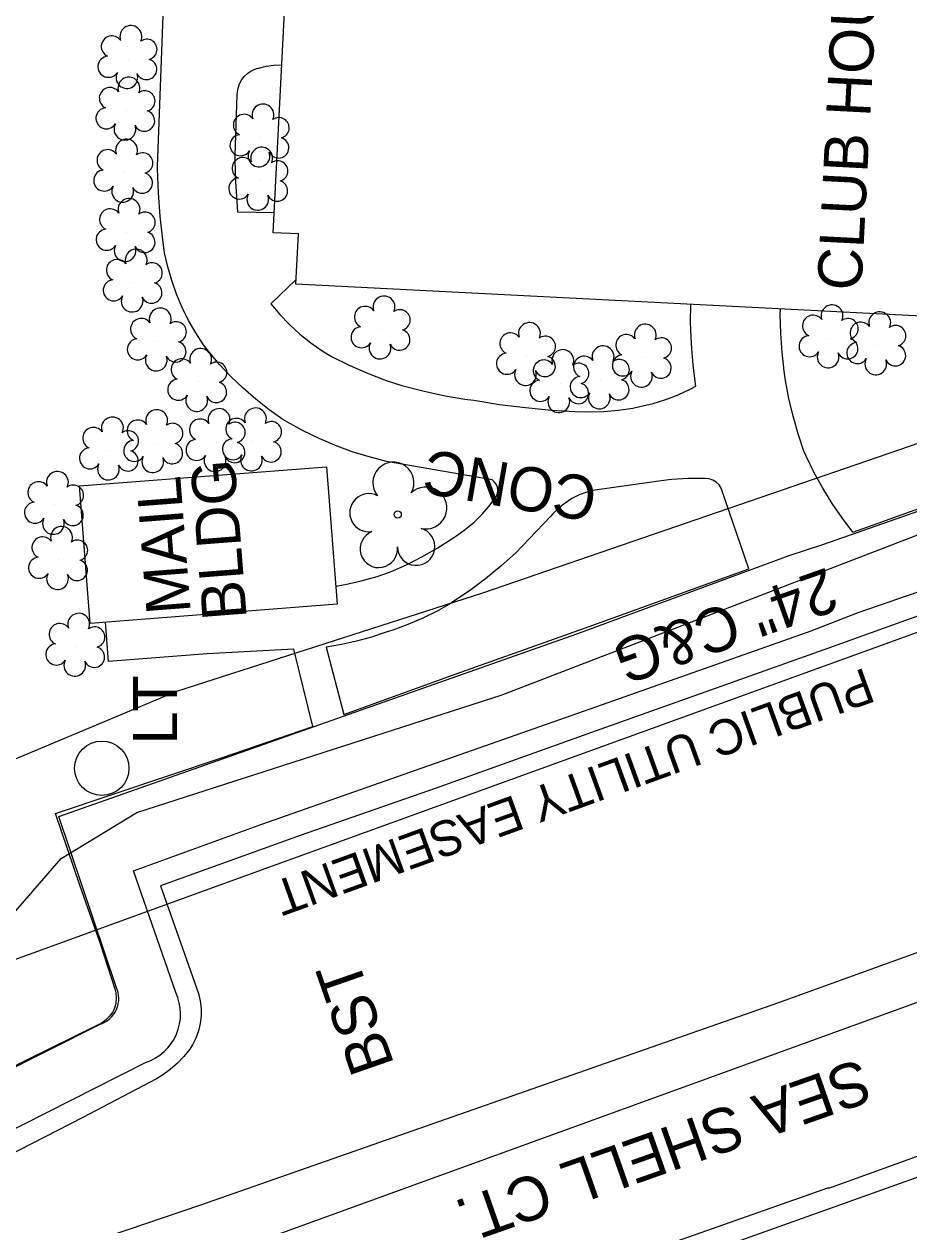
# Model space of a CAD drawing. Extents: x 1614611 to 1617571, y 898867 to 905462.
# Drawn here: x 1616410.3 to 1616490.5, y 903640.3 to 903749 of the extents above; entities that cross this region are included whole.
import ezdxf

# ---------------------------------------------------------------- set-up
doc = ezdxf.new("R2010")
doc.units = 0
for name, color, linetype in [('Exist Boundary Watershed Residential C 05', 7, 'Continuous'), ('Exist Building', 7, 'Continuous'), ('Exist Building Text', 7, 'Continuous'), ('Exist Other Culture Area Outline', 7, 'Continuous'), ('Exist Right of Way Easement Line Text', 7, 'Continuous'), ('Exist Roads EOP Text', 7, 'Continuous'), ('Exist Utilities Other Pole CELL', 7, 'Continuous'), ('Exist Utilities Other Pole Text', 7, 'Continuous'), ('Exist Utilities Telephone UG FO SUE LOS B', 7, 'Continuous'), ('Exist Utilities TV UG FO Cable SUE LOS B', 7, 'Continuous'), ('Exist Utilities Water UG Line SUE LOS B', 7, 'Continuous'), ('Exist Vegetation Shrub CELL', 7, 'Continuous'), ('Exist Vegetation Tree CELL', 7, 'Continuous'), ('Prop Earthen Structure Cut Ditch Special Back of Curb Detail CELL', 7, 'Continuous'), ('Raster_Level_2', 7, 'Continuous'), ('Scratch_Level_1', 7, 'Continuous'), ('Scratch_Level_9', 7, 'Continuous')]:
    doc.layers.add(name, color=color, linetype=linetype)

msp = doc.modelspace()

# ---------------------------------------------------------------- linework, layer by layer
at = {"layer": 'Exist Boundary Watershed Residential C 05'}
msp.add_line((1616404.41, 903646.41), (1616421.34, 903654.97), dxfattribs=at)
for points in [[(1616424.06, 903661.29), (1616420.25, 903672.32), (1616431.85, 903676.54), (1616462.71, 903687.37), (1616481.6, 903694.05), (1616485.86, 903695.71), (1616492.24, 903697.91), (1616511.21, 903704.68), (1616512.84, 903699.7), (1616514.71, 903694.52), (1616516.59, 903689.23)], [(1616522.28, 903655.67), (1616483.74, 903641.89), (1616444.61, 903627.92), (1616416.59, 903617.9)]]:
    msp.add_lwpolyline(points, dxfattribs=at)
msp.add_ellipse((1616419.91, 903659.33), major_axis=(4.56, 0.52), ratio=0.998402, start_param=4.915467, end_param=6.611675, dxfattribs=at)
at = {"layer": 'Exist Building'}
msp.add_lwpolyline([(1616497.51, 903722.23), (1616434.95, 903725.43), (1616435.18, 903729.98), (1616432.89, 903730.1), (1616434.76, 903766.57), (1616520.96, 903762.15), (1616519.1, 903725.79), (1616514.81, 903726.01), (1616514.57, 903721.36), (1616508.97, 903721.64)], dxfattribs=at)
msp.add_lwpolyline([(1616415.35, 903707.17), (1616437.72, 903708.9), (1616438.69, 903696.45), (1616416.31, 903694.72)], close=True, dxfattribs=at)
at = {"layer": 'Exist Other Culture Area Outline'}
for points in [[(1616438.56, 903698.09), (1616439.4, 903698.24), (1616440.86, 903698.58), (1616442.29, 903698.98), (1616443.52, 903699.4), (1616444.96, 903700.04), (1616446.36, 903700.75), (1616447.73, 903701.53), (1616449.06, 903702.37), (1616449.51, 903702.68), (1616450.31, 903703.25), (1616451.07, 903703.89), (1616451.78, 903704.58), (1616452.43, 903705.33), (1616453.02, 903706.12), (1616453.07, 903706.2), (1616453.19, 903706.47), (1616453.24, 903706.76), (1616453.2, 903707.05), (1616453.09, 903707.32), (1616452.91, 903707.55), (1616452.72, 903707.71), (1616450.62, 903708.09), (1616443.14, 903709.39), (1616441.58, 903709.79), (1616440.04, 903710.27), (1616438.53, 903710.83), (1616437.04, 903711.46), (1616435.6, 903712.16), (1616434.18, 903712.94), (1616433.77, 903713.18), (1616432.51, 903714.06), (1616431.31, 903715.01), (1616430.16, 903716.02), (1616429.05, 903717.08), (1616428.01, 903718.2), (1616427.03, 903719.38), (1616426.59, 903719.94), (1616425.87, 903721.03), (1616425.22, 903722.16), (1616424.64, 903723.32), (1616424.13, 903724.53), (1616423.7, 903725.76), (1616423.34, 903727.01), (1616423.06, 903728.28), (1616422.88, 903729.44), (1616422.65, 903731.58), (1616422.5, 903733.72), (1616422.42, 903735.87), (1616422.42, 903736.1), (1616423.02, 903752.18)], [(1616432.98, 903731.89), (1616429.69, 903731.97), (1616429.46, 903735.23), (1616429.43, 903737.12), (1616429.64, 903742.62), (1616429.68, 903743.06), (1616429.8, 903743.48), (1616430, 903743.88), (1616430.26, 903744.24), (1616430.59, 903744.54), (1616430.96, 903744.78), (1616431.37, 903744.95), (1616431.55, 903745), (1616432.25, 903745.18), (1616432.96, 903745.28), (1616433.67, 903745.3)], [(1616434.97, 903725.86), (1616432.66, 903723.65), (1616433.48, 903722.69), (1616434.36, 903721.78), (1616435.3, 903720.92), (1616436.29, 903720.13), (1616437.32, 903719.4), (1616438.16, 903718.88), (1616439.78, 903718.09), (1616441.43, 903717.37), (1616443.12, 903716.73), (1616444.55, 903716.25), (1616446.43, 903715.77), (1616448.32, 903715.37), (1616450.23, 903715.04), (1616451.05, 903714.92), (1616453.39, 903714.55), (1616455.74, 903714.26), (1616458.1, 903714.04), (1616460.19, 903713.91), (1616461.51, 903713.87), (1616462.83, 903713.91), (1616464.15, 903714.03), (1616465.46, 903714.22), (1616466.1, 903714.35), (1616467.28, 903714.63), (1616468.43, 903714.99), (1616469.55, 903715.42), (1616470.64, 903715.93), (1616471.15, 903716.19), (1616470.92, 903718.11), (1616470.76, 903720.04), (1616470.68, 903721.98), (1616470.69, 903723.6)], [(1616485.37, 903702.99), (1616484.4, 903704.27), (1616483.49, 903705.59), (1616482.65, 903706.96), (1616481.88, 903708.36), (1616481.18, 903709.8), (1616480.95, 903710.33), (1616480.42, 903711.9), (1616479.96, 903713.48), (1616479.58, 903715.09), (1616479.28, 903716.71), (1616479.15, 903717.57), (1616478.96, 903719.27), (1616478.84, 903720.98), (1616478.8, 903722.69), (1616478.81, 903723.19)], [(1616485.37, 903702.99), (1616487.68, 903703.79), (1616500.78, 903708.55), (1616508.93, 903711.47), (1616508.22, 903715.83), (1616507.68, 903719.46), (1616507.29, 903721.73)], [(1616402.13, 903650.99), (1616410.64, 903655.24), (1616416.83, 903658.28), (1616417.32, 903658.54), (1616417.76, 903658.87), (1616418.17, 903659.25), (1616418.36, 903659.48), (1616418.55, 903659.9), (1616418.67, 903660.34), (1616418.7, 903660.8), (1616418.66, 903661.26), (1616418.61, 903661.5), (1616417.24, 903665.71), (1616415.38, 903671.03), (1616413.19, 903677.5), (1616428.29, 903682.59), (1616436.48, 903685.38), (1616434.76, 903692.39), (1616426.9, 903691.97), (1616417.97, 903691.26), (1616417.71, 903694.83)]]:
    msp.add_lwpolyline(points, dxfattribs=at)
msp.add_lwpolyline([(1616439.28, 903686.47), (1616449.47, 903690.17), (1616461.51, 903694.43), (1616475.96, 903699.65), (1616473.45, 903706.97), (1616473.26, 903707.27), (1616473, 903707.52), (1616472.7, 903707.7), (1616472.36, 903707.82), (1616472, 903707.85), (1616471.94, 903707.85), (1616470.46, 903707.84), (1616468.99, 903707.75), (1616468.67, 903707.72), (1616462.02, 903706.79), (1616461.3, 903706.61), (1616460.6, 903706.35), (1616459.94, 903706.02), (1616459.31, 903705.62), (1616458.73, 903705.15), (1616458.2, 903704.63), (1616458.01, 903704.41), (1616454.84, 903701.09), (1616453.49, 903699.89), (1616452.1, 903698.75), (1616450.65, 903697.68), (1616449.16, 903696.67), (1616448.99, 903696.56), (1616447.72, 903695.84), (1616446.43, 903695.19), (1616445.09, 903694.62), (1616443.73, 903694.12), (1616443.13, 903693.93), (1616441.79, 903693.48), (1616440.44, 903693.1), (1616439.06, 903692.8), (1616437.68, 903692.58)], close=True, dxfattribs=at)
at = {"layer": 'Exist Utilities Other Pole CELL'}
msp.add_circle((1616417.37, 903681.61), 2.46, dxfattribs=at)
at = {"layer": 'Exist Utilities Telephone UG FO SUE LOS B'}
msp.add_lwpolyline([(1616368.82, 903664.38), (1616374.13, 903666.7), (1616400.24, 903678.58), (1616424.15, 903688.58), (1616451.87, 903697.49), (1616492.43, 903711.43), (1616524.09, 903720.83), (1616535.63, 903725.41), (1616539.88, 903728.72), (1616540.44, 903740.67), (1616541.79, 903762.56), (1616543.01, 903774.12), (1616544.39, 903782.9), (1616550.25, 903790.71), (1616577.87, 903805.8), (1616588.44, 903809.04)], dxfattribs=at)
at = {"layer": 'Exist Utilities TV UG FO Cable SUE LOS B'}
msp.add_lwpolyline([(1616409.28, 903583.28), (1616401.83, 903602.06), (1616396.84, 903616.07), (1616392.29, 903636.86), (1616392.86, 903647.11), (1616394.48, 903651.32), (1616413.7, 903673.44), (1616420.55, 903677.59), (1616453.53, 903688.22), (1616514.87, 903711.84), (1616526.07, 903715.66), (1616536.86, 903720.55), (1616545.52, 903724.83), (1616549.16, 903728.55), (1616549.91, 903729.9), (1616554.28, 903748.73), (1616554.29, 903750.67), (1616552.37, 903762.47), (1616557.09, 903779.98), (1616577.36, 903795.05), (1616590.41, 903803.23)], dxfattribs=at)
at = {"layer": 'Exist Utilities Water UG Line SUE LOS B'}
msp.add_lwpolyline([(1616350.21, 903616.94), (1616374.62, 903624.54), (1616426.35, 903642.07), (1616478.57, 903660.36), (1616520.74, 903675.61), (1616534.8, 903680.84), (1616536.9, 903682.38), (1616549.12, 903691.48), (1616560.45, 903718.95), (1616573.2, 903736.65), (1616589.15, 903758.02), (1616604.81, 903760.79)], dxfattribs=at)
at = {"layer": 'Exist Vegetation Shrub CELL'}
for p, q in [((1616419.77, 903745.82), (1616419.77, 903745.82)), ((1616419.59, 903741.15), (1616419.59, 903741.15)), ((1616431.73, 903738.72), (1616431.73, 903738.72)), ((1616419.39, 903735.53), (1616419.39, 903735.53)), ((1616431.62, 903734.81), (1616431.62, 903734.81)), ((1616419.61, 903730.16), (1616419.61, 903730.16)), ((1616420.25, 903725.58), (1616420.25, 903725.58)), ((1616442.69, 903721.33), (1616442.69, 903721.33)), ((1616483.26, 903720.53), (1616483.26, 903720.53)), ((1616422.43, 903720.24), (1616422.43, 903720.24)), ((1616487.58, 903719.9), (1616487.58, 903719.9)), ((1616455.86, 903718.93), (1616455.86, 903718.93)), ((1616466.35, 903718.78), (1616466.35, 903718.78)), ((1616426.09, 903716.58), (1616426.09, 903716.58)), ((1616458.88, 903716.48), (1616458.88, 903716.48)), ((1616462.53, 903716.82), (1616462.53, 903716.82)), ((1616422.11, 903711.04), (1616422.11, 903711.04)), ((1616427.75, 903711.14), (1616427.75, 903711.14)), ((1616431.05, 903711.2), (1616431.05, 903711.2)), ((1616418.1, 903710.38), (1616418.1, 903710.38)), ((1616413.12, 903705.45), (1616413.12, 903705.45)), ((1616413.49, 903700.47), (1616413.49, 903700.47)), ((1616415.05, 903692.61), (1616415.05, 903692.61))]:
    msp.add_line(p, q, dxfattribs=at)
for centre, radius, start, end in [((1616420, 903747.86), 0.99, 334.8391, 200.4717), ((1616418.29, 903746.95), 0.968, 35.8908, 245.4216), ((1616421.44, 903746.69), 0.929, 284.4567, 126.0861), ((1616417.97, 903745.12), 0.955, 95.1099, 327.9534), ((1616421.41, 903744.89), 0.937, 204.9913, 73.4601), ((1616419.64, 903744.14), 0.984, 151.2797, 21.387), ((1616419.82, 903743.19), 0.99, 334.8391, 200.4717), ((1616418.11, 903742.28), 0.968, 35.8908, 245.4216), ((1616421.26, 903742.02), 0.929, 284.4567, 126.0861), ((1616417.79, 903740.45), 0.955, 95.1099, 327.9534), ((1616421.22, 903740.22), 0.937, 204.9913, 73.4601), ((1616431.96, 903740.76), 0.99, 334.8391, 200.4717), ((1616419.46, 903739.47), 0.984, 151.2797, 21.387), ((1616430.25, 903739.85), 0.968, 35.8908, 245.4216), ((1616433.4, 903739.59), 0.929, 284.4567, 126.0861), ((1616429.93, 903738.02), 0.955, 95.1099, 327.9534), ((1616419.61, 903737.57), 0.99, 334.8391, 200.4717), ((1616431.85, 903736.85), 0.99, 334.8391, 200.4717), ((1616433.37, 903737.79), 0.937, 204.9913, 73.4601), ((1616417.9, 903736.65), 0.968, 35.8908, 245.4216), ((1616421.06, 903736.4), 0.929, 284.4567, 126.0861), ((1616430.14, 903735.93), 0.968, 35.8908, 245.4216), ((1616431.6, 903737.04), 0.984, 151.2797, 21.387), ((1616433.29, 903735.68), 0.929, 284.4567, 126.0861), ((1616417.59, 903734.82), 0.955, 95.1099, 327.9534), ((1616421.02, 903734.6), 0.937, 204.9913, 73.4601), ((1616429.82, 903734.1), 0.955, 95.1099, 327.9534), ((1616433.26, 903733.88), 0.937, 204.9913, 73.4601), ((1616419.26, 903733.84), 0.984, 151.2797, 21.387), ((1616431.49, 903733.12), 0.984, 151.2797, 21.387), ((1616418.13, 903731.29), 0.968, 35.8908, 245.4216), ((1616419.84, 903732.2), 0.99, 334.8391, 200.4717), ((1616421.28, 903731.03), 0.929, 284.4567, 126.0861), ((1616417.81, 903729.46), 0.955, 95.1099, 327.9534), ((1616421.25, 903729.23), 0.937, 204.9913, 73.4601), ((1616419.48, 903728.48), 0.984, 151.2797, 21.387), ((1616420.48, 903727.62), 0.99, 334.8391, 200.4717), ((1616418.76, 903726.71), 0.968, 35.8908, 245.4216), ((1616421.92, 903726.45), 0.929, 284.4567, 126.0861), ((1616418.45, 903724.88), 0.955, 95.1099, 327.9534), ((1616421.88, 903724.65), 0.937, 204.9913, 73.4601), ((1616420.12, 903723.9), 0.984, 151.2797, 21.387), ((1616442.92, 903723.37), 0.99, 334.8391, 200.4717), ((1616483.49, 903722.57), 0.99, 334.8391, 200.4717), ((1616422.66, 903722.28), 0.99, 334.8391, 200.4717), ((1616441.21, 903722.46), 0.968, 35.8908, 245.4216), ((1616444.36, 903722.2), 0.929, 284.4567, 126.0861), ((1616481.78, 903721.66), 0.968, 35.8908, 245.4216), ((1616487.81, 903721.94), 0.99, 334.8391, 200.4717), ((1616420.94, 903721.37), 0.968, 35.8908, 245.4216), ((1616424.1, 903721.11), 0.929, 284.4567, 126.0861), ((1616440.89, 903720.63), 0.955, 95.1099, 327.9534), ((1616456.09, 903720.97), 0.99, 334.8391, 200.4717), ((1616466.58, 903720.82), 0.99, 334.8391, 200.4717), ((1616484.93, 903721.4), 0.929, 284.4567, 126.0861), ((1616486.1, 903721.03), 0.968, 35.8908, 245.4216), ((1616489.25, 903720.77), 0.929, 284.4567, 126.0861), ((1616420.63, 903719.54), 0.955, 95.1099, 327.9534), ((1616444.33, 903720.4), 0.937, 204.9913, 73.4601), ((1616454.38, 903720.06), 0.968, 35.8908, 245.4216), ((1616457.53, 903719.8), 0.929, 284.4567, 126.0861), ((1616464.87, 903719.91), 0.968, 35.8908, 245.4216), ((1616468.03, 903719.65), 0.929, 284.4567, 126.0861), ((1616481.46, 903719.82), 0.955, 95.1099, 327.9534), ((1616484.9, 903719.6), 0.937, 204.9913, 73.4601), ((1616424.06, 903719.32), 0.937, 204.9913, 73.4601), ((1616426.32, 903718.62), 0.99, 334.8391, 200.4717), ((1616442.56, 903719.65), 0.984, 151.2797, 21.387), ((1616454.06, 903718.23), 0.955, 95.1099, 327.9534), ((1616459.11, 903718.52), 0.99, 334.8391, 200.4717), ((1616462.76, 903718.86), 0.99, 334.8391, 200.4717), ((1616483.13, 903718.85), 0.984, 151.2797, 21.387), ((1616485.78, 903719.2), 0.955, 95.1099, 327.9534), ((1616489.22, 903718.97), 0.937, 204.9913, 73.4601), ((1616422.3, 903718.56), 0.984, 151.2797, 21.387), ((1616424.61, 903717.71), 0.968, 35.8908, 245.4216), ((1616427.76, 903717.45), 0.929, 284.4567, 126.0861), ((1616457.4, 903717.61), 0.968, 35.8908, 245.4216), ((1616457.5, 903718), 0.937, 204.9913, 73.4601), ((1616460.55, 903717.35), 0.929, 284.4567, 126.0861), ((1616461.05, 903717.95), 0.968, 35.8908, 245.4216), ((1616464.55, 903718.08), 0.955, 95.1099, 327.9534), ((1616464.21, 903717.69), 0.929, 284.4567, 126.0861), ((1616467.99, 903717.85), 0.937, 204.9913, 73.4601), ((1616487.45, 903718.22), 0.984, 151.2797, 21.387), ((1616455.73, 903717.25), 0.984, 151.2797, 21.387), ((1616460.73, 903716.12), 0.955, 95.1099, 327.9534), ((1616466.23, 903717.1), 0.984, 151.2797, 21.387), ((1616424.29, 903715.88), 0.955, 95.1099, 327.9534), ((1616427.73, 903715.65), 0.937, 204.9913, 73.4601), ((1616457.08, 903715.78), 0.955, 95.1099, 327.9534), ((1616460.52, 903715.55), 0.937, 204.9913, 73.4601), ((1616464.17, 903715.89), 0.937, 204.9913, 73.4601), ((1616425.96, 903714.9), 0.984, 151.2797, 21.387), ((1616458.75, 903714.8), 0.984, 151.2797, 21.387), ((1616462.41, 903715.14), 0.984, 151.2797, 21.387), ((1616422.34, 903713.08), 0.99, 334.8391, 200.4717), ((1616427.98, 903713.18), 0.99, 334.8391, 200.4717), ((1616431.28, 903713.24), 0.99, 334.8391, 200.4717), ((1616418.33, 903712.42), 0.99, 334.8391, 200.4717), ((1616420.63, 903712.17), 0.968, 35.8908, 245.4216), ((1616423.78, 903711.91), 0.929, 284.4567, 126.0861), ((1616426.27, 903712.26), 0.968, 35.8908, 245.4216), ((1616429.56, 903712.32), 0.968, 35.8908, 245.4216), ((1616429.42, 903712.01), 0.929, 284.4567, 126.0861), ((1616432.72, 903712.07), 0.929, 284.4567, 126.0861), ((1616416.61, 903711.5), 0.968, 35.8908, 245.4216), ((1616419.77, 903711.24), 0.929, 284.4567, 126.0861), ((1616416.3, 903709.67), 0.955, 95.1099, 327.9534), ((1616420.31, 903710.34), 0.955, 95.1099, 327.9534), ((1616423.75, 903710.11), 0.937, 204.9913, 73.4601), ((1616425.95, 903710.43), 0.955, 95.1099, 327.9534), ((1616429.25, 903710.49), 0.955, 95.1099, 327.9534), ((1616429.39, 903710.21), 0.937, 204.9913, 73.4601), ((1616432.68, 903710.27), 0.937, 204.9913, 73.4601), ((1616419.73, 903709.45), 0.937, 204.9913, 73.4601), ((1616421.98, 903709.36), 0.984, 151.2797, 21.387), ((1616427.62, 903709.45), 0.984, 151.2797, 21.387), ((1616430.92, 903709.51), 0.984, 151.2797, 21.387), ((1616413.35, 903707.49), 0.99, 334.8391, 200.4717), ((1616417.97, 903708.69), 0.984, 151.2797, 21.387), ((1616411.64, 903706.58), 0.968, 35.8908, 245.4216), ((1616414.79, 903706.32), 0.929, 284.4567, 126.0861), ((1616411.32, 903704.75), 0.955, 95.1099, 327.9534), ((1616414.76, 903704.52), 0.937, 204.9913, 73.4601), ((1616412.99, 903703.77), 0.984, 151.2797, 21.387), ((1616413.72, 903702.51), 0.99, 334.8391, 200.4717), ((1616412.01, 903701.59), 0.968, 35.8908, 245.4216), ((1616415.16, 903701.34), 0.929, 284.4567, 126.0861), ((1616411.69, 903699.76), 0.955, 95.1099, 327.9534), ((1616415.13, 903699.54), 0.937, 204.9913, 73.4601), ((1616413.36, 903698.78), 0.984, 151.2797, 21.387), ((1616415.28, 903694.65), 0.99, 334.8391, 200.4717), ((1616413.57, 903693.74), 0.968, 35.8908, 245.4216), ((1616416.72, 903693.48), 0.929, 284.4567, 126.0861), ((1616413.25, 903691.91), 0.955, 95.1099, 327.9534), ((1616416.69, 903691.68), 0.937, 204.9913, 73.4601), ((1616414.92, 903690.93), 0.984, 151.2797, 21.387)]:
    msp.add_arc(centre, radius, start, end, dxfattribs=at)
at = {"layer": 'Exist Vegetation Tree CELL'}
msp.add_line((1616444.16, 903704.58), (1616444.16, 903704.58), dxfattribs=at)
msp.add_circle((1616444.16, 903704.58), 0.326, dxfattribs=at)
for centre, radius, start, end in [((1616443.77, 903707.46), 1.86, 330.1651, 219.7134), ((1616441.55, 903704.74), 1.73, 62.6636, 279.3457), ((1616446.71, 903705.17), 1.9, 257.1011, 134.1999), ((1616442.45, 903701.46), 1.69, 111.5671, 6.231), ((1616445.83, 903701.68), 1.7, 181.2822, 74.56)]:
    msp.add_arc(centre, radius, start, end, dxfattribs=at)
at = {"layer": 'Prop Earthen Structure Cut Ditch Special Back of Curb Detail CELL'}
for p, q in [((1616426.35, 903670.41), (1616515.61, 903702.78)), ((1616358.79, 903645.91), (1616426.35, 903670.41))]:
    msp.add_line(p, q, dxfattribs=at)
at = {"layer": 'Raster_Level_2'}
msp.add_line((1616340.93, 903605.93), (1616526.35, 903673.17), dxfattribs=at)
at = {"layer": 'Scratch_Level_1'}
msp.add_line((1616402.29, 903650.93), (1616417.15, 903658.41), dxfattribs=at)
for points in [[(1616418.68, 903661.83), (1616413.47, 903677.24), (1616429.92, 903683.04), (1616460.47, 903693.81), (1616479.62, 903700.86), (1616482.65, 903701.86), (1616489.9, 903704.39), (1616513.62, 903712.83), (1616515.92, 903706.42), (1616517.71, 903701.38), (1616519.34, 903696.67)], [(1616492.84, 903695.94), (1616483.16, 903692.48), (1616473.85, 903689.17), (1616462.55, 903685.15), (1616447.54, 903679.77), (1616435.34, 903675.52), (1616422.68, 903670.97), (1616426.11, 903661.21), (1616426.28, 903660.55), (1616426.36, 903659.86), (1616426.36, 903659.18), (1616426.28, 903658.5), (1616426.13, 903657.83), (1616425.89, 903657.18), (1616425.59, 903656.57), (1616425.34, 903656.18), (1616424.81, 903655.51), (1616424.21, 903654.89), (1616423.56, 903654.32), (1616422.86, 903653.82), (1616422.32, 903653.5), (1616415.64, 903650), (1616405.26, 903644.66)]]:
    msp.add_lwpolyline(points, dxfattribs=at)
msp.add_ellipse((1616416.44, 903660.77), major_axis=(2.26, -1), ratio=0.996738, start_param=5.418431, end_param=7.141958, dxfattribs=at)
at = {"layer": 'Scratch_Level_9'}
msp.add_lwpolyline([(1616521.59, 903657.43), (1616483.18, 903643.55), (1616483.16, 903643.61), (1616444.03, 903629.83), (1616415.81, 903619.72)], dxfattribs=at)

# ---------------------------------------------------------------- texts
at = {"layer": 'Exist Building Text'}
for s, rotation, p in [('CLUB HOUSE', 87.0684, (1616486.14, 903724.79)), ('CONC', 170.2041, (1616462.43, 903707.83)), ('BLDG', 94.4363, (1616430.5, 903695.18)), ('MAIL', 94.4363, (1616425.43, 903695.71))]:
    msp.add_text(s, height=4, rotation=rotation, dxfattribs=at).set_placement(p)
at = {"layer": 'Exist Right of Way Easement Line Text'}
msp.add_text('PUBLIC UTILITY EASEMENT', height=3.2, rotation=199.9333, dxfattribs=at).set_placement((1616486.49, 903690.75))
at = {"layer": 'Exist Roads EOP Text'}
for s, rotation, p in [('24" C&G', 199.404, (1616483.05, 903699.82)), ('BST', 109.1768, (1616443.88, 903654.77)), ('SEA SHELL CT.', 199.404, (1616486.09, 903655.37))]:
    msp.add_text(s, height=4, rotation=rotation, dxfattribs=at).set_placement(p)
at = {"layer": 'Exist Utilities Other Pole Text'}
msp.add_text('LT', height=4, rotation=90, dxfattribs=at).set_placement((1616424.19, 903683.77))

doc.saveas('drawing.dxf')
